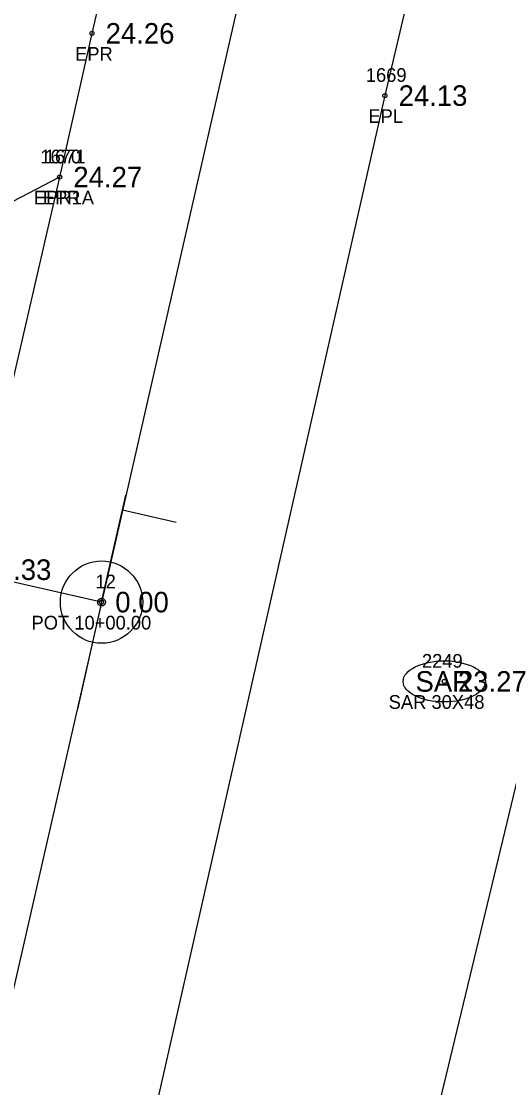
# Model space of a CAD drawing. Extents: x 2654414 to 2656963, y 761776 to 764965.
# Drawn here: x 2655470.4 to 2655506, y 762159.7 to 762237.5 of the extents above; entities that cross this region are included whole.
import ezdxf

# ---------------------------------------------------------------- set-up
doc = ezdxf.new("R2010")
doc.units = 0
for name, color, linetype in [('Default', 7, 'Continuous'), ('RD_EX_Road', 7, 'Continuous'), ('RD_EX_Road_txCode', 7, 'Continuous'), ('RD_EX_SU_Sewer', 7, 'Continuous'), ('RD_EX_TX_Road_ELEV', 7, 'Continuous'), ('RD_EX_TX_UT_ELEV', 7, 'Continuous'), ('RD_EX_UT_txCode', 7, 'Continuous'), ('RD_EX_VEG', 7, 'Continuous'), ('RD_HC_Cl', 7, 'Continuous'), ('RD_HC_Data', 7, 'Continuous'), ('RD_HC_Data_Tic', 7, 'Continuous'), ('RD_HC_Survey_ELEV', 7, 'Continuous'), ('RD_HC_txCode', 7, 'Continuous'), ('RD_SMD_Locator', 7, 'Continuous')]:
    doc.layers.add(name, color=color, linetype=linetype)

msp = doc.modelspace()

# ---------------------------------------------------------------- linework, layer by layer
at = {"layer": 'Default'}
msp.add_line((2656050.51, 764712.367), (2655383.263, 761787.511), dxfattribs=at)
at = {"layer": 'RD_EX_Road'}
for points in [[(2655700.994, 763232.279), (2655693.552, 763198.573), (2655671.649, 763102.037), (2655649.038, 763001.061), (2655627.271, 762906.233), (2655604.996, 762809.365), (2655598.992, 762783.09), (2655583.655, 762714.137), (2655561.97, 762618.323), (2655556.356, 762593.843), (2655548.114, 762557.141), (2655540.102, 762522.478), (2655518.03, 762425.04), (2655496.479, 762329.558), (2655475.552, 762236.625), (2655473.199, 762226.142), (2655466.574, 762197.504), (2655460.058, 762168.164), (2655454.261, 762143.776), (2655432.5, 762049.878), (2655410.7, 761955.515), (2655388.166, 761858.426), (2655373.501, 761793.951)], [(2655670.037, 762995.178), (2655648.569, 762900.673), (2655631.27, 762824.032), (2655626.665, 762802.872), (2655621.781, 762781.907), (2655611.705, 762738.435), (2655604.931, 762708.622), (2655582.644, 762610.543), (2655576.456, 762583.319), (2655561.406, 762517.242), (2655539.154, 762414.805), (2655531.984, 762386.147), (2655517.984, 762324.295), (2655508.173, 762280.146), (2655501.462, 762251.601), (2655496.922, 762232.086), (2655477.204, 762144.974), (2655472.137, 762122.524), (2655453.741, 762045.099), (2655431.791, 761949.924), (2655409.76, 761853.25), (2655401.248, 761816.416), (2655394.612, 761787.366)], [(2655473.199, 762226.142), (2655455.546, 762216.939), (2655447.671, 762217.38)]]:
    msp.add_lwpolyline(points, dxfattribs=at)
at = {"layer": 'RD_EX_SU_Sewer'}
msp.add_ellipse((2655501.254, 762189.352), major_axis=(-3, 0), ratio=0.5, dxfattribs=at)
at = {"layer": 'RD_EX_VEG'}
msp.add_line((2655518.281, 762230.882), (2655497.58, 762144.903), dxfattribs=at)
at = {"layer": 'RD_HC_Cl'}
for p, q in [((2656050.51, 764712.367), (2655383.263, 761787.511)), ((2655476.255, 762195.138), (2655321.054, 762230.163))]:
    msp.add_line(p, q, dxfattribs=at)
at = {"layer": 'RD_HC_Data'}
for radius in [3, 0.282]:
    msp.add_circle((2655476.255, 762195.138), radius, dxfattribs=at)
at = {"layer": 'RD_HC_Data_Tic'}
for p, q in [((2655476.255, 762195.138), (2655478.016, 762202.942)), ((2655477.79, 762201.866), (2655481.69, 762200.976)), ((2655476.255, 762195.138), (2655474.494, 762187.334))]:
    msp.add_line(p, q, dxfattribs=at)
at = {"layer": 'RD_SMD_Locator'}
for centre in [(2655475.552, 762236.625), (2655496.922, 762232.086), (2655473.199, 762226.142), (2655473.199, 762226.142), (2655476.255, 762195.138), (2655501.254, 762189.352)]:
    msp.add_circle(centre, 0.15, dxfattribs=at)

# ---------------------------------------------------------------- texts
at = {"layer": 'RD_EX_Road_txCode'}
for s, p in [('EPR', (2655474.323, 762234.625)), ('1669', (2655495.528, 762233.086)), ('EPL', (2655495.717, 762230.086)), ('1670', (2655471.79, 762227.142)), ('1671', (2655472.113, 762227.142)), ('EPR1A', (2655471.318, 762224.142)), ('EPR', (2655471.971, 762224.142))]:
    msp.add_text(s, height=1, dxfattribs=at).set_placement(p)
at = {"layer": 'RD_EX_SU_Sewer'}
msp.add_text('SAR', height=1.5, dxfattribs=at).set_placement((2655499.156, 762188.602))
at = {"layer": 'RD_EX_TX_Road_ELEV'}
for s, p in [('24.26', (2655476.552, 762235.875)), ('24.13', (2655497.922, 762231.336)), ('24.27', (2655474.199, 762225.392)), ('24.27', (2655474.199, 762225.392)), ('24.33', (2655467.574, 762196.754))]:
    msp.add_text(s, height=1.5, dxfattribs=at).set_placement(p)
at = {"layer": 'RD_EX_TX_UT_ELEV'}
msp.add_text('23.27', height=1.5, dxfattribs=at).set_placement((2655502.254, 762188.602))
at = {"layer": 'RD_EX_UT_txCode'}
for s, p in [('2249', (2655499.624, 762190.352)), ('SAR 30X48', (2655497.199, 762187.352))]:
    msp.add_text(s, height=1, dxfattribs=at).set_placement(p)
at = {"layer": 'RD_HC_Survey_ELEV'}
msp.add_text('0.00', height=1.5, dxfattribs=at).set_placement((2655477.255, 762194.388))
at = {"layer": 'RD_HC_txCode'}
for s, p in [('12', (2655475.806, 762196.138)), ('POT 10+00.00', (2655471.145, 762193.138))]:
    msp.add_text(s, height=1, dxfattribs=at).set_placement(p)

doc.saveas('drawing.dxf')
